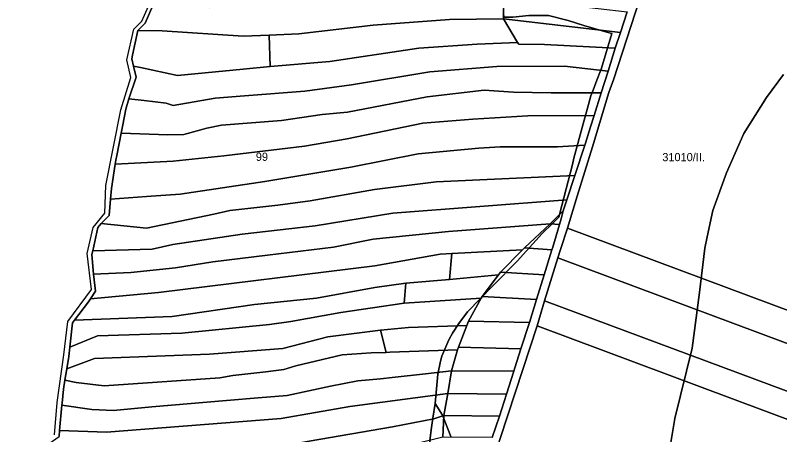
# Model space of a CAD drawing. Extents: x -541351 to -537540, y -1162694 to -1159725.
# Drawn here: x -540845.8 to -540378.9, y -1160376 to -1160119.8 of the extents above; entities that cross this region are included whole.
import ezdxf

# ---------------------------------------------------------------- set-up
doc = ezdxf.new("R2010")
doc.units = 0
for name, color, linetype in [('95560013', 7, 'Continuous'), ('95610013', 7, 'Continuous'), ('95620013', 7, 'Continuous'), ('95630013', 7, 'Continuous'), ('95640013', 7, 'Continuous'), ('95660013', 7, 'Continuous')]:
    doc.layers.add(name, color=color, linetype=linetype)

msp = doc.modelspace()

# ---------------------------------------------------------------- linework, layer by layer
at = {"layer": '95560013'}
for points in [[(-540356.83, -1160306.42), (-540508.48, -1160249.81), (-540502.49, -1160230.24), (-540493.25, -1160200.09), (-540483.27, -1160166.95), (-540480.24, -1160158.64), (-540461.87, -1160101.94), (-540442.45, -1160037.81), (-540415.15, -1159950.06), (-540408.75, -1159946.72), (-540359.07, -1159965.85), (-540332.08, -1159975.44), (-540333.53, -1159979.4), (-540310.02, -1160032.13), (-540317.01, -1160072.74), (-540332.5, -1160163.53), (-540349.68, -1160266.25)], [(-540514.38, -1160267.98), (-540360.1, -1160325.54), (-540363.17, -1160344.9), (-540364.58, -1160352.98), (-540522.49, -1160294.25)], [(-540522.49, -1160294.25), (-540364.58, -1160352.98), (-540367.38, -1160369.03), (-540527.1, -1160309.52)], [(-540527.1, -1160309.52), (-540367.38, -1160369.03), (-540379.07, -1160438.35), (-540385.21, -1160475.93), (-540388.61, -1160496.72), (-540565.8, -1160430.3), (-540549.55, -1160378.18), (-540535.84, -1160336.23)]]:
    msp.add_lwpolyline(points, close=True, dxfattribs=at)
at = {"layer": '95610013'}
for points in [[(-540472.02, -1160117.6), (-540476.19, -1160130.2), (-540547.6, -1160121.95), (-540547.45, -1160108.79), (-540542.89, -1160109.37)], [(-540539.05, -1160136.36), (-540547.6, -1160121.95), (-540476.19, -1160130.2), (-540479.47, -1160139.87), (-540522.52, -1160137.61), (-540538.29, -1160137.36)], [(-540356.83, -1160306.42), (-540360.1, -1160325.54), (-540514.38, -1160267.98), (-540512.69, -1160262.74), (-540508.48, -1160249.81)], [(-540560.55, -1160291.57), (-540550.57, -1160278.26), (-540549.39, -1160276.68), (-540522.68, -1160278.3), (-540527.45, -1160293.46)], [(-540561.13, -1160292.61), (-540560.55, -1160291.57), (-540527.45, -1160293.46), (-540531.74, -1160307.42), (-540568.98, -1160306.56)], [(-540568.98, -1160306.56), (-540531.74, -1160307.42), (-540536.91, -1160323.41), (-540575.12, -1160322.52), (-540569.99, -1160309.2)], [(-540540.6, -1160335.03), (-540541.32, -1160337.11), (-540579.33, -1160336.97), (-540575.6, -1160324.17), (-540575.12, -1160322.52), (-540536.91, -1160323.41)], [(-540541.32, -1160337.11), (-540545.77, -1160351.23), (-540581.6, -1160350.89), (-540579.33, -1160336.97)], [(-540581.6, -1160350.89), (-540545.77, -1160351.23), (-540550, -1160364.68), (-540583.96, -1160364.33)], [(-540583.96, -1160364.33), (-540550, -1160364.68), (-540554.48, -1160377.62), (-540584.69, -1160377.51)]]:
    msp.add_lwpolyline(points, close=True, dxfattribs=at)
at = {"layer": '95620013'}
for points in [[(-540580.56, -1160122.37), (-540627.16, -1160125.9), (-540672.5, -1160131.19), (-540690.64, -1160131.86), (-540706.51, -1160132.45), (-540756.13, -1160129.17), (-540770.89, -1160129.16), (-540766.4, -1160124.54), (-540761.74, -1160113.85), (-540727.16, -1160115.06), (-540690.89, -1160114.05), (-540636.23, -1160110.02), (-540542.51, -1160105.39), (-540542.89, -1160109.37), (-540547.45, -1160108.79), (-540547.6, -1160121.95)], [(-540580.56, -1160122.37), (-540547.6, -1160121.95), (-540539.05, -1160136.36), (-540563.7, -1160137.41), (-540599.24, -1160139.82), (-540653.67, -1160147.91), (-540690.06, -1160151.15), (-540690.64, -1160131.86), (-540672.5, -1160131.19), (-540627.16, -1160125.9)], [(-540690.64, -1160131.86), (-540690.06, -1160151.15), (-540706.49, -1160152.62), (-540746.62, -1160156.56), (-540769.27, -1160151.57), (-540773.53, -1160150.83), (-540774.58, -1160146.42), (-540774.14, -1160144.2), (-540770.89, -1160129.16), (-540756.13, -1160129.17), (-540706.51, -1160132.45)], [(-540771.91, -1160157.64), (-540773.53, -1160150.83), (-540769.27, -1160151.57), (-540746.62, -1160156.56), (-540706.49, -1160152.62), (-540690.06, -1160151.15), (-540653.67, -1160147.91), (-540599.24, -1160139.82), (-540563.7, -1160137.41), (-540539.05, -1160136.36), (-540538.29, -1160137.36), (-540522.52, -1160137.61), (-540479.47, -1160139.87), (-540483.73, -1160153.92), (-540510.23, -1160150.83), (-540551.74, -1160151.15), (-540592.67, -1160154.28), (-540640.42, -1160162.16), (-540668.98, -1160166.04), (-540705.66, -1160168.98), (-540723.6, -1160170.45), (-540749.23, -1160174.83), (-540753.68, -1160173.47), (-540767.08, -1160171.86), (-540776.35, -1160170.89)], [(-540778.31, -1160177.1), (-540776.35, -1160170.89), (-540767.08, -1160171.86), (-540753.68, -1160173.47), (-540749.23, -1160174.83), (-540723.6, -1160170.45), (-540705.66, -1160168.98), (-540668.98, -1160166.04), (-540640.42, -1160162.16), (-540592.67, -1160154.28), (-540551.74, -1160151.15), (-540510.23, -1160150.83), (-540483.73, -1160153.92), (-540487.91, -1160167.24), (-540518.39, -1160167.12), (-540541.4, -1160166.79), (-540559.48, -1160165.48), (-540594.17, -1160169.59), (-540642.91, -1160178.96), (-540658.36, -1160180.44), (-540683.18, -1160184.05), (-540719.73, -1160186.99), (-540728.77, -1160188.8), (-540742.9, -1160192.58), (-540752.56, -1160192.75), (-540781.03, -1160191.83), (-540779.99, -1160186.63)], [(-540683.18, -1160184.05), (-540658.36, -1160180.44), (-540642.91, -1160178.96), (-540594.17, -1160169.59), (-540559.48, -1160165.48), (-540541.4, -1160166.79), (-540518.39, -1160167.12), (-540487.91, -1160167.24), (-540492.22, -1160180.92), (-540532.68, -1160181.26), (-540566.4, -1160183.25), (-540596.81, -1160185.58), (-540642.96, -1160195.14), (-540669.2, -1160199.62), (-540718.42, -1160205.58), (-540749.25, -1160208.82), (-540784.7, -1160210.81), (-540784.29, -1160208.32), (-540783.75, -1160205.4), (-540781.03, -1160191.83), (-540752.56, -1160192.75), (-540742.9, -1160192.58), (-540728.77, -1160188.8), (-540719.73, -1160186.99)], [(-540549.55, -1160200.15), (-540562.57, -1160201.03), (-540599.71, -1160204.46), (-540640.82, -1160212.58), (-540693.27, -1160221.38), (-540744.97, -1160229.12), (-540765.7, -1160230.38), (-540787.61, -1160232.01), (-540787.08, -1160225.49), (-540784.7, -1160210.81), (-540749.25, -1160208.82), (-540718.42, -1160205.58), (-540669.2, -1160199.62), (-540642.96, -1160195.14), (-540596.81, -1160185.58), (-540566.4, -1160183.25), (-540532.68, -1160181.26), (-540492.22, -1160180.92), (-540494.43, -1160187.95), (-540497.59, -1160197.96), (-540497.93, -1160199.01), (-540514.58, -1160200.15)], [(-540693.27, -1160221.38), (-540640.82, -1160212.58), (-540599.71, -1160204.46), (-540562.57, -1160201.03), (-540549.55, -1160200.15), (-540514.58, -1160200.15), (-540497.93, -1160199.01), (-540503.99, -1160217.62), (-540588.8, -1160221.45), (-540626.27, -1160226.24), (-540665.61, -1160233.12), (-540685.5, -1160235.78), (-540714.64, -1160239.11), (-540724.43, -1160241.19), (-540765.65, -1160249.71), (-540793.21, -1160247.04), (-540788.44, -1160242.11), (-540787.61, -1160232.01), (-540765.7, -1160230.38), (-540744.97, -1160229.12)], [(-540685.5, -1160235.78), (-540665.61, -1160233.12), (-540626.27, -1160226.24), (-540588.8, -1160221.45), (-540503.99, -1160217.62), (-540508.83, -1160232.47), (-540615.24, -1160240.62), (-540662.7, -1160248.33), (-540707.15, -1160253.48), (-540749.62, -1160259.73), (-540762.11, -1160262.65), (-540798.49, -1160263.63), (-540795.43, -1160249.34), (-540793.21, -1160247.04), (-540765.65, -1160249.71), (-540724.43, -1160241.19), (-540714.64, -1160239.11)], [(-540798.03, -1160277.88), (-540798.97, -1160265.9), (-540798.49, -1160263.63), (-540762.11, -1160262.65), (-540749.62, -1160259.73), (-540707.15, -1160253.48), (-540662.7, -1160248.33), (-540615.24, -1160240.62), (-540508.83, -1160232.47), (-540511.04, -1160239.25), (-540519.12, -1160247.15), (-540581.17, -1160251.88), (-540627.14, -1160256.43), (-540651.31, -1160261.34), (-540691.67, -1160266.37), (-540725.05, -1160270.32), (-540747.82, -1160274.03), (-540775.24, -1160276.79)], [(-540519.12, -1160247.15), (-540511.04, -1160239.25), (-540512.38, -1160244.07), (-540513.3, -1160247.6)], [(-540798.03, -1160277.88), (-540775.24, -1160276.79), (-540747.82, -1160274.03), (-540725.05, -1160270.32), (-540691.67, -1160266.37), (-540651.31, -1160261.34), (-540627.14, -1160256.43), (-540581.17, -1160251.88), (-540519.12, -1160247.15), (-540534.77, -1160261.89), (-540535.92, -1160263.05), (-540579.04, -1160265.3), (-540586.2, -1160265.67), (-540626.19, -1160272.86), (-540758.37, -1160289.18), (-540799.86, -1160292.99), (-540796.82, -1160288.21)], [(-540534.77, -1160261.89), (-540519.12, -1160247.15), (-540513.3, -1160247.6), (-540517.48, -1160261.33), (-540518.04, -1160263.09)], [(-540522.68, -1160278.3), (-540549.39, -1160276.68), (-540535.92, -1160263.05), (-540534.77, -1160261.89), (-540518.04, -1160263.09)], [(-540801.04, -1160294.85), (-540799.86, -1160292.99), (-540758.37, -1160289.18), (-540626.19, -1160272.86), (-540586.2, -1160265.67), (-540579.04, -1160265.3), (-540580.59, -1160281.1), (-540607.17, -1160283.48), (-540626.16, -1160286.13), (-540661.69, -1160292.47), (-540699.65, -1160296.42), (-540749.98, -1160303.73), (-540809.55, -1160306.08)], [(-540535.92, -1160263.05), (-540549.39, -1160276.68), (-540550.57, -1160278.26), (-540580.59, -1160281.1), (-540579.04, -1160265.3)], [(-540561.13, -1160292.61), (-540608.33, -1160295.61), (-540607.17, -1160283.48), (-540580.59, -1160281.1), (-540550.57, -1160278.26), (-540560.55, -1160291.57)], [(-540690.46, -1160308.66), (-540743.95, -1160313.91), (-540795.59, -1160315.47), (-540812.49, -1160322.4), (-540810.72, -1160307.62), (-540809.55, -1160306.08), (-540749.98, -1160303.73), (-540699.65, -1160296.42), (-540661.69, -1160292.47), (-540626.16, -1160286.13), (-540607.17, -1160283.48), (-540608.33, -1160295.61), (-540646.92, -1160301.37), (-540677.4, -1160306.74)], [(-540605.69, -1160310.4), (-540622.7, -1160312.1), (-540654.8, -1160316.1), (-540682.32, -1160323.25), (-540727.13, -1160326.85), (-540797.46, -1160329.5), (-540814.27, -1160335.68), (-540813.1, -1160328.27), (-540812.49, -1160322.4), (-540795.59, -1160315.47), (-540743.95, -1160313.91), (-540690.46, -1160308.66), (-540677.4, -1160306.74), (-540646.92, -1160301.37), (-540608.33, -1160295.61), (-540561.13, -1160292.61), (-540568.98, -1160306.56), (-540569.99, -1160309.2)], [(-540622.7, -1160312.1), (-540619.32, -1160325.65), (-540628.5, -1160325.96), (-540646.2, -1160327.08), (-540674.35, -1160333.97), (-540681.74, -1160336.16), (-540692.8, -1160337.58), (-540712.93, -1160339.84), (-540720.83, -1160341.19), (-540791.54, -1160346.07), (-540808.52, -1160344.14), (-540815.39, -1160342.72), (-540814.27, -1160335.68), (-540797.46, -1160329.5), (-540727.13, -1160326.85), (-540682.32, -1160323.25), (-540654.8, -1160316.1)], [(-540575.6, -1160324.17), (-540616.98, -1160325.57), (-540619.32, -1160325.65), (-540622.7, -1160312.1), (-540605.69, -1160310.4), (-540569.99, -1160309.2), (-540575.12, -1160322.52)], [(-540615.66, -1160341.06), (-540622.73, -1160341.86), (-540636.53, -1160343.14), (-540653.17, -1160346.25), (-540679.77, -1160351.96), (-540697.46, -1160353.38), (-540716.67, -1160355), (-540762.37, -1160358.85), (-540785.73, -1160361.13), (-540798.97, -1160360.56), (-540817.27, -1160357.85), (-540817.17, -1160356.74), (-540816.25, -1160348.12), (-540815.39, -1160342.72), (-540808.52, -1160344.14), (-540791.54, -1160346.07), (-540720.83, -1160341.19), (-540712.93, -1160339.84), (-540692.8, -1160337.58), (-540681.74, -1160336.16), (-540674.35, -1160333.97), (-540646.2, -1160327.08), (-540628.5, -1160325.96), (-540619.32, -1160325.65), (-540616.98, -1160325.57), (-540575.6, -1160324.17), (-540579.33, -1160336.97), (-540595.29, -1160338.76)], [(-540653.17, -1160346.25), (-540636.53, -1160343.14), (-540622.73, -1160341.86), (-540615.66, -1160341.06), (-540595.29, -1160338.76), (-540579.33, -1160336.97), (-540581.6, -1160350.89), (-540641.4, -1160358.74), (-540683.29, -1160366.1), (-540790.11, -1160374.42), (-540818.69, -1160373.35), (-540817.27, -1160357.85), (-540798.97, -1160360.56), (-540785.73, -1160361.13), (-540762.37, -1160358.85), (-540716.67, -1160355), (-540697.46, -1160353.38), (-540679.77, -1160351.96)], [(-540590.15, -1160366.32), (-540615.31, -1160371.08), (-540666.27, -1160379.96), (-540676.17, -1160381.82), (-540709.19, -1160384.91), (-540740.96, -1160390.28), (-540808.12, -1160396.25), (-540814.52, -1160395.42), (-540833.75, -1160387.41), (-540819.02, -1160376.97), (-540818.69, -1160373.35), (-540790.11, -1160374.42), (-540683.29, -1160366.1), (-540641.4, -1160358.74), (-540581.6, -1160350.89), (-540583.96, -1160364.33)], [(-540707.82, -1160400.44), (-540739.84, -1160405.36), (-540771.86, -1160409.01), (-540807.6, -1160413.49), (-540845.75, -1160409.04), (-540837.52, -1160391.15), (-540836.74, -1160389.53), (-540833.75, -1160387.41), (-540814.52, -1160395.42), (-540808.12, -1160396.25), (-540740.96, -1160390.28), (-540709.19, -1160384.91), (-540676.17, -1160381.82), (-540666.27, -1160379.96), (-540615.31, -1160371.08), (-540590.15, -1160366.32), (-540583.96, -1160364.33), (-540584.69, -1160377.51), (-540601.9, -1160381.82), (-540635.12, -1160387.39), (-540665.45, -1160394.82)]]:
    msp.add_lwpolyline(points, close=True, dxfattribs=at)
at = {"layer": '95630013'}
for points in [[(-540821.88, -1160376.01), (-540820.09, -1160356.29), (-540816.02, -1160327.12), (-540813.62, -1160306.86), (-540799.24, -1160287.31), (-540801.78, -1160265.2), (-540798.25, -1160249.3), (-540791.12, -1160240.65), (-540790.41, -1160223.8), (-540781.23, -1160177.62), (-540775.1, -1160157.8), (-540777.6, -1160147.04), (-540773.44, -1160128.26), (-540768.54, -1160123.44), (-540755.16, -1160093.5)], [(-540761.74, -1160113.85), (-540766.4, -1160124.54), (-540770.89, -1160129.16), (-540774.14, -1160144.2), (-540774.58, -1160146.42), (-540773.53, -1160150.83), (-540771.91, -1160157.64), (-540776.35, -1160170.89), (-540778.31, -1160177.1), (-540779.99, -1160186.63), (-540781.03, -1160191.83), (-540783.75, -1160205.4), (-540784.29, -1160208.32), (-540784.7, -1160210.81), (-540787.08, -1160225.49), (-540787.61, -1160232.01), (-540788.44, -1160242.11), (-540793.21, -1160247.04), (-540795.43, -1160249.34), (-540798.49, -1160263.63), (-540798.97, -1160265.9), (-540798.03, -1160277.88), (-540796.82, -1160288.21), (-540799.86, -1160292.99), (-540801.04, -1160294.85), (-540809.55, -1160306.08), (-540810.72, -1160307.62), (-540812.49, -1160322.4), (-540813.1, -1160328.27), (-540814.27, -1160335.68), (-540815.39, -1160342.72), (-540816.25, -1160348.12), (-540817.17, -1160356.74), (-540817.27, -1160357.85), (-540818.69, -1160373.35), (-540819.02, -1160376.97)]]:
    msp.add_lwpolyline(points, dxfattribs=at)
at = {"layer": '95640013'}
for points in [[(-540461.87, -1160101.94), (-540480.24, -1160158.64), (-540483.27, -1160166.95), (-540493.25, -1160200.09), (-540502.49, -1160230.24), (-540508.48, -1160249.81), (-540512.69, -1160262.74), (-540514.38, -1160267.98), (-540522.49, -1160294.25), (-540527.1, -1160309.52), (-540535.84, -1160336.23), (-540549.55, -1160378.18), (-540565.8, -1160430.3), (-540570.22, -1160444.43), (-540575.72, -1160462.04), (-540574.14, -1160478.6), (-540562.96, -1160602.4), (-540555.87, -1160675.5), (-540552.51, -1160710.69), (-540550.96, -1160727.07), (-540549.68, -1160743.9), (-540544.91, -1160797.79), (-540544.72, -1160800.38), (-540540.33, -1160848.73)], [(-540554.48, -1160377.62), (-540550, -1160364.68), (-540545.77, -1160351.23), (-540541.32, -1160337.11), (-540540.6, -1160335.03), (-540536.91, -1160323.41), (-540531.74, -1160307.42), (-540527.45, -1160293.46), (-540522.68, -1160278.3), (-540518.04, -1160263.09), (-540517.48, -1160261.33), (-540513.3, -1160247.6), (-540512.38, -1160244.07), (-540511.04, -1160239.25), (-540508.83, -1160232.47), (-540503.99, -1160217.62), (-540497.93, -1160199.01), (-540497.59, -1160197.96), (-540494.43, -1160187.95), (-540492.22, -1160180.92), (-540487.91, -1160167.24), (-540483.73, -1160153.92), (-540479.47, -1160139.87), (-540476.19, -1160130.2), (-540472.02, -1160117.6)]]:
    msp.add_lwpolyline(points, dxfattribs=at)
at = {"layer": '95660013'}
for points in [[(-540821.88, -1160376.01), (-540820.09, -1160356.29), (-540816.02, -1160327.12), (-540813.62, -1160306.86), (-540799.24, -1160287.31), (-540801.78, -1160265.2), (-540798.25, -1160249.3), (-540791.12, -1160240.65), (-540790.41, -1160223.8), (-540781.23, -1160177.62), (-540775.1, -1160157.8), (-540777.6, -1160147.04), (-540773.44, -1160128.26), (-540768.54, -1160123.44), (-540755.16, -1160093.5)], [(-540547.69, -1160119), (-540547.44, -1160119.89), (-540547.12, -1160121), (-540541.81, -1160121), (-540532.19, -1160120), (-540524, -1160120), (-540520, -1160120), (-540508.12, -1160123), (-540498.5, -1160126), (-540484.37, -1160130), (-540481.37, -1160131), (-540487.81, -1160152), (-540491.12, -1160161), (-540492.83, -1160165.44), (-540494.19, -1160169), (-540496.27, -1160176.56), (-540498.87, -1160186), (-540504.62, -1160207), (-540505.37, -1160211), (-540512, -1160236), (-540513.81, -1160243), (-540517.62, -1160247), (-540524, -1160253), (-540539.31, -1160270), (-540554, -1160285), (-540569.62, -1160301), (-540574.87, -1160308), (-540578.81, -1160314), (-540581, -1160318), (-540585.31, -1160328), (-540586.12, -1160331), (-540587.62, -1160339), (-540589.37, -1160357), (-540590.66, -1160365.89), (-540591.69, -1160373), (-540593.66, -1160388.11)], [(-540579.81, -1160377), (-540584.81, -1160364), (-540589.37, -1160357), (-540587.62, -1160339), (-540586.12, -1160331), (-540585.31, -1160328), (-540581, -1160318), (-540578.81, -1160314), (-540574.87, -1160308), (-540569.62, -1160301), (-540554, -1160285), (-540539.31, -1160270), (-540524, -1160253), (-540517.62, -1160247), (-540513.81, -1160243), (-540512, -1160236), (-540505.37, -1160211), (-540504.62, -1160207), (-540498.87, -1160186), (-540496.27, -1160176.56), (-540494.19, -1160169), (-540492.83, -1160165.44), (-540491.12, -1160161), (-540487.81, -1160152), (-540481.37, -1160131), (-540484.37, -1160130), (-540498.5, -1160126), (-540508.12, -1160123), (-540520, -1160120), (-540524, -1160120), (-540532.19, -1160120), (-540541.81, -1160121), (-540547.12, -1160121), (-540547.44, -1160119.89), (-540547.69, -1160119)], [(-540446.62, -1160388), (-540443, -1160366), (-540432.31, -1160323), (-540427.81, -1160289), (-540424.62, -1160262), (-540423.12, -1160255), (-540419.81, -1160239), (-540411.31, -1160216), (-540400.87, -1160192), (-540386.87, -1160170), (-540376.5, -1160156)], [(-540376.5, -1160156), (-540386.87, -1160170), (-540400.87, -1160192), (-540411.31, -1160216), (-540419.81, -1160239), (-540423.12, -1160255), (-540424.62, -1160262), (-540427.81, -1160289), (-540432.31, -1160323), (-540443, -1160366), (-540446.62, -1160388)], [(-540593.66, -1160388.11), (-540591.69, -1160373), (-540590.66, -1160365.89), (-540589.37, -1160357), (-540584.81, -1160364), (-540579.81, -1160377)]]:
    msp.add_lwpolyline(points, dxfattribs=at)

# ---------------------------------------------------------------- texts
for s, rotation, p in [('99', 360, (-540698.84, -1160208.69)), ('31010/II.', 0, (-540450.59, -1160208.9))]:
    msp.add_text(s, height=5, rotation=rotation, dxfattribs=at).set_placement(p)

doc.saveas('drawing.dxf')
